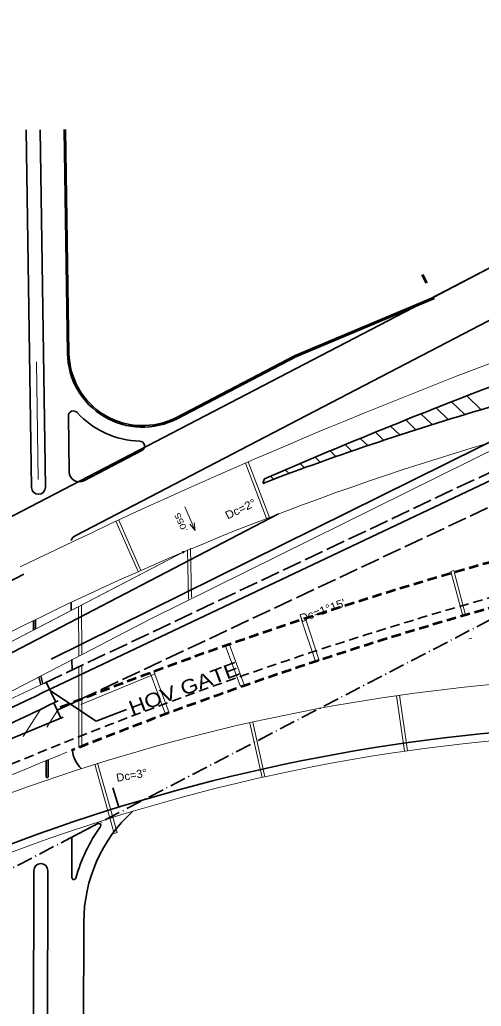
# Model space of a CAD drawing. Extents: x 2354993 to 2372084, y 6966390 to 6990057.
# Drawn here: x 2361674 to 2362136, y 6977334 to 6978319 of the extents above; entities that cross this region are included whole.
import ezdxf

# ---------------------------------------------------------------- set-up
doc = ezdxf.new("R2010")
doc.units = 0
doc.header["$LTSCALE"] = 3.2
doc.header["$PDMODE"] = 32
doc.header["$PDSIZE"] = 1.6
for name, pattern in [('DASH_DOUBLE_DOT', [9.2, 5, -1.2, 0.3, -1.2, 0.3, -1.2]), ('DOT_DASHED', [7.7, 5, -1.2, 0.3, -1.2]), ('LONG_DASHED', [7.5, 6, -1.5]), ('MEDIUM_DASHED', [4.5, 3, -1.5])]:
    doc.linetypes.add(name, pattern=pattern)
for name, color, linetype, lineweight in [('10', 7, 'Continuous', 13), ('12', 7, 'Continuous', 13), ('17', 7, 'Continuous', 13), ('19', 7, 'Continuous', 13), ('2', 7, 'Continuous', 35), ('5', 7, 'Continuous', 35), ('6', 7, 'Continuous', 35), ('61', 7, 'Continuous', 13), ('8', 7, 'Continuous', 13), ('9', 7, 'Continuous', 13)]:
    doc.layers.add(name, color=color, linetype=linetype, lineweight=lineweight)

msp = doc.modelspace()

# ---------------------------------------------------------------- linework, layer by layer
at = {"layer": '10', "linetype": 'DASH_DOUBLE_DOT', "lineweight": 53}
msp.add_line((2362076.387, 6978064.824), (2362080.803, 6978056.327), dxfattribs=at)
at = {"layer": '12'}
for p, q in [((2361921.078, 6977821.033), (2361899.822, 6977876.283)), ((2361923.878, 6977822.11), (2361902.576, 6977877.48)), ((2361792.739, 6977767.876), (2361770.482, 6977818.12)), ((2361795.484, 6977769.089), (2361773.205, 6977819.384)), ((2361842.059, 6977789.602), (2361842.938, 6977740.473)), ((2361845.031, 6977791.148), (2361845.91, 6977742.017)), ((2362105.187, 6977768.143), (2362108.085, 6977768.92)), ((2362117.11, 6977723.657), (2362105.187, 6977768.143)), ((2362119.992, 6977724.493), (2362108.085, 6977768.92)), ((2361736.019, 6977734.494), (2361736.188, 6977684.995)), ((2361733.026, 6977732.938), (2361733.194, 6977683.439)), ((2362126.194, 6977701.35), (2362123.296, 6977700.573)), ((2361733.232, 6977672.053), (2361733.508, 6977592.186)), ((2361736.227, 6977673.502), (2361736.503, 6977593.373)), ((2361904.379, 6977616.377), (2361916.495, 6977562.288)), ((2361907.22, 6977617.417), (2361919.423, 6977562.942)), ((2361752.054, 6977576.473), (2361771.567, 6977507.169)), ((2361749.245, 6977575.374), (2361768.678, 6977506.355)), ((2361768.678, 6977506.355), (2361771.567, 6977507.169))]:
    msp.add_line(p, q, dxfattribs=at)
at = {"layer": '17', "lineweight": 35}
for p, q in [((2361706.685, 6977651.285), (2362482.125, 6978018.666)), ((2361715.491, 6977621.611), (2361708.436, 6977636.64))]:
    msp.add_line(p, q, dxfattribs=at)
at = {"layer": '17'}
msp.add_line((2361735.503, 6977634.987), (2361809.727, 6977665.63), dxfattribs=at)
at = {"layer": '17', "lineweight": 35}
for radius in [4621.662, 4607.662]:
    msp.add_arc((2363672.711, 6973468.642), radius, 115.17558, 118.91596, dxfattribs=at)
at = {"layer": '19'}
msp.add_line((2361849.61, 6977808.832), (2361844.368, 6977815.28), dxfattribs=at)
msp.add_lwpolyline([(2361839.453, 6977832.529), (2361849.61, 6977808.832), (2361848.554, 6977817.07)], dxfattribs=at)
at = {"layer": '2'}
for p, q in [((2358006.591, 6975920.846), (2363488.891, 6978770.331)), ((2361700.849, 6977657.382), (2361710.205, 6977637.472)), ((2361750.672, 6977618.382), (2361704.885, 6977648.793)), ((2361750.672, 6977618.382), (2361781.152, 6977630.088))]:
    msp.add_line(p, q, dxfattribs=at)
at = {"layer": '2', "linetype": 'LONG_DASHED'}
for p, q in [((2361699.088, 6977656.554), (2362455.357, 6978014.169)), ((2361711.836, 6977629.398), (2362366.21, 6977936.92))]:
    msp.add_line(p, q, dxfattribs=at)
at = {"layer": '5'}
for p, q in [((2362087.371, 6978041.876), (2363419.143, 6978734.078)), ((2361685.969, 6977851.923), (2361680.68, 6978209.191)), ((2361699.965, 6977852.247), (2361694.678, 6978209.398)), ((2361721.987, 6977986.095), (2361718.675, 6978209.753)), ((2361723.487, 6977986.117), (2361720.175, 6978209.775)), ((2361730.202, 6977803.996), (2362197.968, 6978047.082)), ((2361949.566, 6977983.686), (2362087.37, 6978041.875)), ((2361950.212, 6977982.331), (2362088.839, 6978040.867)), ((2361830.878, 6977921.989), (2361949.571, 6977983.689)), ((2361831.57, 6977920.658), (2361950.212, 6977982.331)), ((2361723.744, 6977867.403), (2361722.915, 6977923.363)), ((2361738.355, 6977858.679), (2361796.334, 6977888.817)), ((2361918.804, 6977860.536), (2361917.281, 6977856.148)), ((2360066.537, 6976855.596), (2361933.038, 6977825.615)), ((2361678.27, 6977765.374), (2360875.69, 6977349.365)), ((2361725.789, 6977729.178), (2361725.672, 6977737.124)), ((2361688.076, 6977709.578), (2361687.938, 6977718.887)), ((2361690.062, 6977710.61), (2361689.924, 6977719.864)), ((2361726.672, 6977669.519), (2361726.517, 6977679.969)), ((2361693.524, 6977662.822), (2361695.477, 6977654.856)), ((2361695.297, 6977663.744), (2361697.27, 6977655.699)), ((2361700.592, 6977562.864), (2361700.624, 6977578.98)), ((2361702.591, 6977563.043), (2361702.591, 6977579.779)), ((2361752.443, 6977516.058), (2361727.548, 6977503.125)), ((2361726.393, 6977462.142), (2361726.47, 6977501.354)), ((2361687.545, 6977030.675), (2361688.407, 6977469.268)), ((2361701.545, 6977030.648), (2361702.406, 6977469.37)), ((2361738.037, 6977280.581), (2361738.307, 6977417.899))]:
    msp.add_line(p, q, dxfattribs=at)
at = {"layer": '5', "lineweight": 13}
for p, q in [((2362121.255, 6977943.555), (2362135.481, 6977929.599)), ((2362090.63, 6977931.574), (2362102.673, 6977919.759)), ((2362105.924, 6977937.584), (2362119.037, 6977924.719)), ((2362075.371, 6977925.53), (2362086.393, 6977914.717)), ((2362044.966, 6977913.333), (2362054.075, 6977904.397)), ((2362060.151, 6977919.449), (2362070.194, 6977909.597)), ((2362183.72, 6977908.026), (2361804.561, 6977720.528)), ((2362029.819, 6977907.181), (2362038.036, 6977899.119)), ((2361999.631, 6977894.769), (2362006.193, 6977888.331)), ((2362014.707, 6977900.992), (2362022.075, 6977893.764)), ((2361969.589, 6977882.216), (2361974.661, 6977877.24)), ((2361984.593, 6977888.51), (2361990.389, 6977882.824)), ((2361954.621, 6977875.887), (2361959.009, 6977871.582)), ((2361924.792, 6977863.122), (2361928.107, 6977859.87)), ((2361939.689, 6977869.522), (2361943.433, 6977865.849)), ((2361548.215, 6977636.892), (2361839.634, 6977788.342)), ((2361546.398, 6977586.361), (2361804.561, 6977720.528)), ((2361677.647, 6977602.994), (2361694.913, 6977630.236)), ((2361701.411, 6977612.468), (2361711.966, 6977629.121))]:
    msp.add_line(p, q, dxfattribs=at)
at = {"layer": '5'}
for points in [[(2362488.793, 6978067.704), (2362331.734, 6977990.029), (2361705.614, 6977680.376)], [(2361443.444, 6977501.522), (2361538.676, 6977545.959), (2361596.235, 6977572.076), (2361717.573, 6977622.314)]]:
    msp.add_lwpolyline(points, dxfattribs=at)
at = {"layer": '5', "lineweight": 13}
msp.add_lwpolyline([(2360275.595, 6976975.512), (2361546.229, 6977635.86), (2361837.648, 6977787.31)], dxfattribs=at)
for centre, radius, start, end in [((2364188.171, 6972614.757), 5737.613, 103.3303, 115.98006), ((2362948.983, 6975157.719), 2854.789, 106.05463, 117.46086), ((2363672.711, 6973468.642), 4629.662, 115.17558, 118.91596), ((2362324.651, 6975741.618), 1921.859, 85.24473, 116.95937), ((2362324.651, 6975741.618), 1865.859, 81.33444, 119.61246), ((2363306.843, 6973626.915), 4266, 111.81838, 116.96246)]:
    msp.add_arc(centre, radius, start, end, dxfattribs=at)
at = {"layer": '5'}
for centre, radius, start, end in [((2361796.978, 6977987.205), 75, 180.84795, 297.46641), ((2361796.978, 6977987.205), 73.5, 180.84795, 297.46641), ((2364188.16, 6972614.79), 5715.578, 110.94799, 113.39373), ((2362948.983, 6975157.719), 2888.789, 106.05464, 110.92598), ((2361727.915, 6977923.437), 5, 42.71676, 180.84825), ((2361796.978, 6977987.205), 89, 222.71676, 268.20112), ((2361794.028, 6977893.254), 5, 297.4663, 88.20112), ((2361733.743, 6977867.552), 10, 180.84851, 297.46669), ((2361692.966, 6977852.144), 7, 180.85752, 0.84812), ((2361734.814, 6977795.123), 10, 117.46043, 157.69627), ((2362324.651, 6975741.618), 1873.859, 81.33444, 116.95937), ((2361756.65, 6977592.618), 30, 185.92381, 225.98214), ((2361756.65, 6977592.618), 30, 215.8194, 225.98214), ((2361701.592, 6977563.041), 1, 211.16298, 0.13618), ((2361888.307, 6977417.605), 150, 132.39016, 179.88758), ((2361888.307, 6977417.605), 164, 144.38064, 164.43941), ((2361753.365, 6977514.283), 2, 324.38064, 117.45137), ((2361728.47, 6977501.35), 2, 117.45162, 179.88671), ((2361695.407, 6977469.255), 7, 359.8968, 179.8874), ((2361728.393, 6977462.139), 2, 179.88746, 344.43822), ((2361728.393, 6977462.135), 2, 179.88746, 344.43941)]:
    msp.add_arc(centre, radius, start, end, dxfattribs=at)
at = {"layer": '5', "linetype": 'MEDIUM_DASHED', "lineweight": 53}
for radius, start, end in [(4310, 96.81172, 111.72863), (4266, 96.81171, 111.74968)]:
    msp.add_arc((2363306.843, 6973626.915), radius, start, end, dxfattribs=at)
at = {"layer": '5', "linetype": 'MEDIUM_DASHED'}
msp.add_arc((2363306.843, 6973626.915), 4276, 96.81172, 116.96246, dxfattribs=at)
at = {"layer": '6', "linetype": 'DOT_DASHED'}
for p, q in [((2360272.717, 6976747.357), (2363548.144, 6978448.903)), ((2360272.718, 6976747.358), (2363548.137, 6978448.9)), ((2360272.718, 6976747.358), (2363548.137, 6978448.9))]:
    msp.add_line(p, q, dxfattribs=at)
at = {"layer": '61'}
for p, q in [((2361969.77, 6977677.965), (2361956.019, 6977719.761)), ((2361973.57, 6977679.216), (2361959.818, 6977721.011)), ((2361879.712, 6977694.491), (2361895.008, 6977653.235)), ((2361883.462, 6977695.881), (2361898.759, 6977654.626)), ((2361804.702, 6977666.679), (2361819.999, 6977625.423)), ((2361808.452, 6977668.069), (2361823.749, 6977626.814)), ((2362058.98, 6977588.466), (2362051.006, 6977643.896)), ((2362061.949, 6977588.891), (2362053.976, 6977644.321))]:
    msp.add_line(p, q, dxfattribs=at)
at = {"layer": '61', "lineweight": 35}
msp.add_line((2361773.414, 6977532.563), (2361767.454, 6977551.926), dxfattribs=at)
at = {"layer": '8'}
msp.add_line((2361691.11, 6977977.442), (2361692.85, 6977859.968), dxfattribs=at)
at = {"layer": '9'}
msp.add_point((2361837.653, 6977787.312), dxfattribs=at)

# ---------------------------------------------------------------- texts
at = {"layer": '17'}
for s, rotation, width, p in [('Dc=2°', 25.472, 1.1, (2361882.048, 6977819.9)), ("Dc=1°15'", 20.149, 1.1, (2361955.69, 6977717.017)), ('Dc=3°', 10.149, 1.05, (2361771.529, 6977557.786))]:
    msp.add_text(s, height=8, rotation=rotation, dxfattribs=dict(at, width=width)).set_placement(p)
at = {"layer": '19', "width": 1.3}
msp.add_text('.055', height=5.999, rotation=114.154, dxfattribs=at).set_placement((2361842.344, 6977808.858))
at = {"layer": '2', "width": 1.2}
msp.add_text('HOV GATE', height=14, rotation=20.62, dxfattribs=at).set_placement((2361786.588, 6977624.386))

doc.saveas('drawing.dxf')
